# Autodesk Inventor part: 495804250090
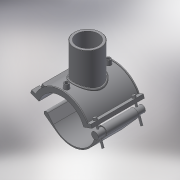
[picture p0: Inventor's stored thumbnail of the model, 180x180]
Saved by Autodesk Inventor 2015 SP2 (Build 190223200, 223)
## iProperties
Created: 2017-07
Part Number: 495804250090
Material: Generic
Description: PLASSON BRANCH SADDLE 250-90
Document SubType Name: Modeling
Designer: KIM
Density: 1 g/cm^3
Appearance: Default
Author: KIM
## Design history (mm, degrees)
derived "495804.ipt"
feature "Solid1::495804.ipt"
feature "Solid2::495804.ipt"
tag "TaggingFeature1"
body "Solid1"
body "Solid2"
other parameters: "B_" = 252, "H_" = 105, "L_" = 176, "d_t" = 6, "d148" = 6.25, "d160" = 6.25, "d2" = 327.6, "d3" = 62.5, "d4" = 176, "d5" = 0, "d6" = 0.1, "d8" = 0, "d19" = 6, "d20" = 6, "d21" = 105.6, "d23" = 0, "d24" = 52.8, "d26" = 0, "d27" = 3, "d28" = 3, "d29" = 3, "d30" = 83.33333, "d31" = 6, "d32" = 0, "d33" = 0, "d34" = 0.6, "d40" = 145.6, "d41" = 99, "d43" = 0, "d45" = 0, "d47" = 245, "d50" = 0, "d70" = 15, "d72" = 0, "d73" = 6, "d75" = 5, "d76" = 0, "d77" = 12.5, "d78" = 155, "d79" = 15, "d80" = 70.4, "d82" = 5 deg, "d84" = 4, "d85" = 14, "d86" = 0, "d87" = 3, "d88" = 0, "d89" = 1, "d90" = 1, "d91" = 140.8, "d92" = 0, "d93" = 0.5, "d94" = 131.57895, "d96" = 285.6, "d97" = 3.52, "d98" = 0, "d102" = 2.7, "d103" = 72, "d105" = 0, "d109" = -35, "d117" = 0.9, "d120" = 140 deg, "d121" = 24.228, "d122" = 20 deg, "d124" = 168, "d126" = 0, "d143" = 262.5, "d150" = 45, "d159" = 6, "d161" = 6.25, "d162" = 105.6, "d163" = 0, "d168" = 127.27273, "d173" = 1, "d175" = 125, "d176" = 20 deg, "d177" = 17.5, "d180" = 0, "d185" = 57.2, "d186" = 57.2, "d188" = 9, "d189" = 17.5, "d190" = 0, "d200" = 15, "d202" = 0, "d216" = 158.4, "d217" = 0, "d221" = 65.12, "d222" = 17.5, "d223" = 10.5, "d224" = 125, "d225" = 10.5, "d227" = 36, "d236" = 20 deg, "d237" = 147, "d238" = 20 deg, "d239" = 17.5
